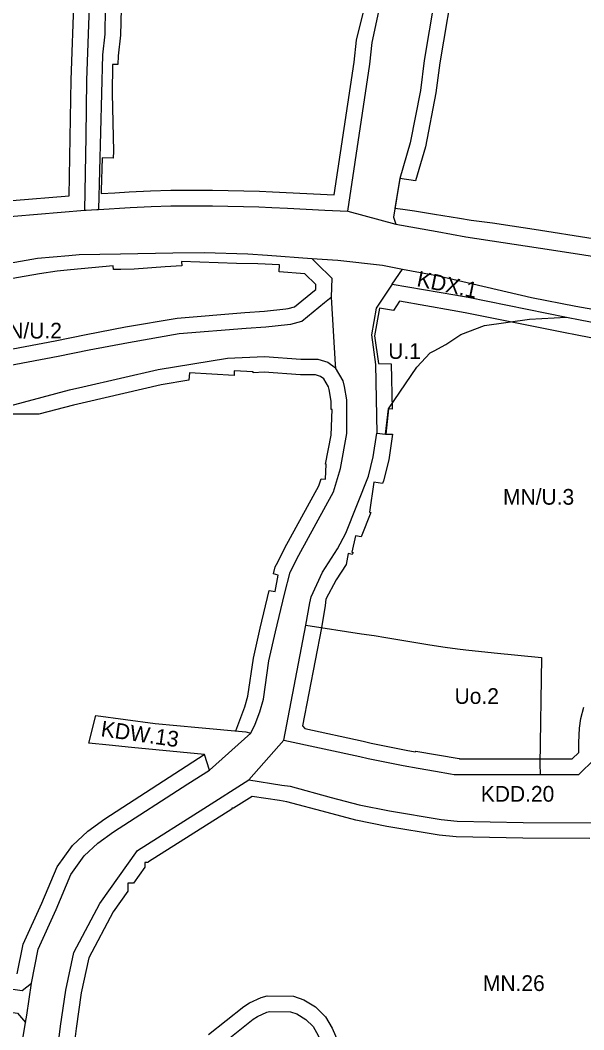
# Model space of a CAD drawing. Extents: x 7414808 to 7417449, y 5544732 to 5546764.
# Drawn here: x 7415895.6 to 7416075.2, y 5545739 to 5546060.4 of the extents above; entities that cross this region are included whole.
import ezdxf

# ---------------------------------------------------------------- set-up
doc = ezdxf.new("R2010")
doc.units = 0
for name, color, linetype in [('LIN_Linie Rozgraniczajace', 7, 'Continuous'), ('LIN_nieprzekraczale linie zabudowy', 7, 'Continuous'), ('TXT_Oznaczenia Przeznaczenia', 7, 'Continuous')]:
    doc.layers.add(name, color=color, linetype=linetype)

msp = doc.modelspace()

# ---------------------------------------------------------------- linework, layer by layer
at = {"layer": 'LIN_Linie Rozgraniczajace'}
msp.add_line((7415955.91, 5545821.67), (7415969.1, 5545833.41), dxfattribs=at)
for points in [[(7416000, 5545999.56), (7416007.01, 5546046.39), (7416007.77, 5546053.27), (7416011.53, 5546070.75), (7416012.03, 5546070.7), (7416016.43, 5546092.22), (7416015.51, 5546092.28), (7416019.25, 5546115.26), (7416019.68, 5546119.96), (7416020.64, 5546130.99), (7416021.01, 5546139.92), (7416020.58, 5546148.86), (7416019.36, 5546157.71), (7416017.52, 5546165.82), (7416014.43, 5546177.2), (7416012.98, 5546181.74)], [(7416031.71, 5546182.56), (7416032.23, 5546181.11), (7416034.82, 5546172.09), (7416036.63, 5546162.89), (7416037.66, 5546153.57), (7416037.89, 5546144.2), (7416037.31, 5546134.83), (7416036.47, 5546126.72), (7416035.62, 5546119.19), (7416034.78, 5546111.66), (7416032.88, 5546099.09), (7416032.19, 5546095.15), (7416030.26, 5546082.93), (7416029.17, 5546076.02), (7416024.41, 5546047.6), (7416023.18, 5546038.06), (7416019.9, 5546021.33), (7416016.59, 5546010.05), (7416014.56, 5545997.73), (7416015.33, 5545995.49)], [(7415918.71, 5546091.48), (7415918.95, 5546098.1), (7415919.91, 5546128.95), (7415920.03, 5546132.92), (7415929.03, 5546132.64), (7415928.75, 5546123.64), (7415924.7, 5546123.6), (7415924.31, 5546123.6), (7415924.15, 5546116.95), (7415924.02, 5546111.29), (7415923.61, 5546097.93), (7415923.01, 5546073.56), (7415922.63, 5546058.16), (7415922.58, 5546056.01), (7415921.81, 5546049.39), (7415920.6, 5546000.18)], [(7415916.2, 5545999.89), (7415916.6, 5546023.36), (7415916.91, 5546041.3), (7415918.4, 5546082.49)], [(7415886.52, 5545997.16), (7415893.57, 5545997.99), (7415916.2, 5545999.89)], [(7415916.2, 5545999.89), (7415916.7, 5545999.93), (7415920.1, 5546000.15), (7415920.6, 5546000.18)], [(7415920.6, 5546000.18), (7415930.62, 5546000.79), (7415937.38, 5546001.08), (7415943.66, 5546001.26), (7415956.86, 5546001.34), (7415971.69, 5546000.97), (7415975.83, 5546000.78), (7415980.77, 5546000.53), (7415992.69, 5545999.93), (7416000, 5545999.56)], [(7416000, 5545999.56), (7416015.33, 5545995.49)], [(7416015.33, 5545995.49), (7416028.49, 5545993.17), (7416037.64, 5545991.43), (7416064.98, 5545987.25), (7416085.59, 5545984.1), (7416096.65, 5545982.41), (7416109.87, 5545979.94), (7416111.59, 5545979.53)], [(7415844.76, 5545971.84), (7415852.47, 5545973.82), (7415865.1, 5545977.09), (7415866.9, 5545977.56), (7415880.97, 5545980.98), (7415882.96, 5545981.47), (7415901.09, 5545984.65), (7415911.16, 5545985.54), (7415914.44, 5545985.83), (7415927.64, 5545986.05), (7415944.27, 5545986.35), (7415954.23, 5545986.43), (7415968.21, 5545986.01), (7415974.4, 5545985.57), (7415988.52, 5545984.56)], [(7415988.52, 5545984.56), (7415990.15, 5545982.96), (7415994.96, 5545978.25), (7415994.76, 5545972.26)], [(7415988.52, 5545984.56), (7415996.88, 5545983.96), (7416011.04, 5545982.43), (7416017.42, 5545981.19)], [(7416014.2, 5545976.41), (7416017.42, 5545981.19)], [(7416017.42, 5545981.19), (7416028.93, 5545978.99), (7416058.62, 5545972.09), (7416072.75, 5545969.33), (7416083.51, 5545967.43), (7416094.03, 5545965.04), (7416101.56, 5545962.07), (7416102.47, 5545961.81)], [(7416014.2, 5545976.41), (7416009.05, 5545968.77), (7416007.57, 5545960.21), (7416008.83, 5545950.76), (7416009.25, 5545928.92)], [(7416014.2, 5545976.41), (7416034.13, 5545972.92), (7416038.34, 5545972.18), (7416069.77, 5545965.84)], [(7415844.58, 5545938.19), (7415852.82, 5545940.7), (7415871.18, 5545946.15), (7415888.53, 5545949.83), (7415907.71, 5545953.42), (7415917.62, 5545955.43), (7415930.1, 5545957.84), (7415946.29, 5545960.61), (7415967.66, 5545962.35), (7415973.92, 5545962.82), (7415980.78, 5545963.53), (7415981.89, 5545963.65), (7415985.36, 5545964.57), (7415992.58, 5545970.49), (7415994.76, 5545972.26)], [(7415994.76, 5545972.26), (7415996.05, 5545950.83), (7415996.13, 5545949.68)], [(7416009.25, 5545928.92), (7416012.07, 5545928.66), (7416012.96, 5545936.69), (7416022.02, 5545949.98), (7416026.33, 5545954.48), (7416027.55, 5545955.12), (7416031.3, 5545957.18), (7416036.08, 5545960.32), (7416043.63, 5545963.18), (7416057.92, 5545965.24), (7416069.77, 5545965.84)], [(7416069.77, 5545965.84), (7416074.06, 5545965.04), (7416086.23, 5545962.71), (7416095.68, 5545960.09), (7416099.01, 5545958.78), (7416101.22, 5545955.99), (7416101.99, 5545952.8)], [(7415887.87, 5545936.49), (7415911.39, 5545942.72), (7415915.59, 5545943.68), (7415939.59, 5545949.25), (7415961.67, 5545952.78), (7415973.46, 5545953.36), (7415985.11, 5545952.48), (7415986.01, 5545952.48), (7415990.47, 5545952.48), (7415993.62, 5545951.52), (7415996.13, 5545949.68)], [(7415969.1, 5545833.41), (7415970.5, 5545836.23), (7415971.99, 5545840.19), (7415973.12, 5545844.18), (7415974.88, 5545856.4), (7415977.01, 5545865.7), (7415979.86, 5545877.67), (7415981.63, 5545884.62), (7415984.42, 5545890.11), (7415995.48, 5545910.24), (7415997.72, 5545917.72), (7415999.71, 5545928.8), (7415999.76, 5545933.26), (7415999.67, 5545939.54), (7415998.98, 5545943.8), (7415998.56, 5545945.63), (7415996.13, 5545949.68)], [(7415986.69, 5545867.84), (7415987.97, 5545874.91), (7415988.31, 5545876.82), (7415991.93, 5545884.66), (7415996.76, 5545892.08), (7415999.35, 5545897.08), (7416006.63, 5545915.23), (7416008.16, 5545921.4), (7416009.25, 5545928.92)], [(7415979.67, 5545831.16), (7415986.69, 5545867.84)], [(7415986.69, 5545867.84), (7416004.35, 5545865.07), (7416008.39, 5545864.46), (7416012.15, 5545863.89), (7416026.14, 5545861.58), (7416031.07, 5545860.77), (7416035.04, 5545860.26), (7416037.64, 5545859.92), (7416046.72, 5545858.95), (7416061.74, 5545857.55), (7416061.28, 5545823.37), (7416061.31, 5545820.54), (7416061.31, 5545820.27)], [(7415955.91, 5545821.67), (7415954.34, 5545826.57), (7415931.12, 5545828.89), (7415923.99, 5545829.6), (7415917.5, 5545830.25), (7415919.7, 5545839.06), (7415938.62, 5545836.47), (7415952.46, 5545835.2), (7415967.56, 5545833.82), (7415969.1, 5545833.41)], [(7415968.5, 5545818.52), (7415979.67, 5545831.16)], [(7415979.67, 5545831.16), (7416003.85, 5545825.95), (7416006.48, 5545825.38), (7416017.69, 5545823.11), (7416022.48, 5545822.25), (7416027.93, 5545821.26), (7416032.74, 5545820.47), (7416033.95, 5545820.27), (7416061.31, 5545820.27)], [(7416061.31, 5545820.27), (7416073.62, 5545820.27), (7416078.62, 5545825.18)], [(7415899.18, 5545753.76), (7415901.32, 5545764.63), (7415907.1, 5545777.22), (7415911.78, 5545788.44), (7415916.04, 5545794.37), (7415920.33, 5545798.37), (7415925.36, 5545801.94), (7415949.1, 5545817.27), (7415955.91, 5545821.67)], [(7415907.51, 5545732.31), (7415908.48, 5545740.08), (7415910.18, 5545751.57), (7415912.74, 5545763.6), (7415920.96, 5545779.17), (7415933.01, 5545796.09), (7415954.12, 5545809.43), (7415968.5, 5545818.52)], [(7415968.5, 5545818.52), (7415979, 5545816.89), (7415981.64, 5545816.49), (7415994.71, 5545812.97), (7416003.69, 5545810.56), (7416013.36, 5545808.66), (7416029.77, 5545805.91), (7416034.85, 5545805.41), (7416055.87, 5545805.01), (7416080.18, 5545804.83), (7416081.41, 5545803.58)], [(7415668.24, 5545779.8), (7415672.05, 5545783.11), (7415685.34, 5545779.85), (7415697.83, 5545777.04), (7415710.13, 5545774.26), (7415722.57, 5545771.47), (7415731.5, 5545769.45), (7415736.13, 5545768.65), (7415748.95, 5545766.65), (7415761.72, 5545764.58), (7415774.82, 5545763.02), (7415795.49, 5545759.28), (7415821.27, 5545755.23), (7415823.26, 5545754.92), (7415847.35, 5545751.4), (7415871.95, 5545747.49), (7415894.72, 5545744.26), (7415897.34, 5545741.25)], [(7415785.08, 5545767.93), (7415793.95, 5545766.44), (7415805.7, 5545764.63), (7415823.54, 5545761.88), (7415841.33, 5545759.46), (7415848.19, 5545758.4), (7415896.23, 5545751.46), (7415899.18, 5545753.76)], [(7415897.34, 5545741.25), (7415897.69, 5545743.65), (7415899.18, 5545753.76)], [(7415907.51, 5545732.31), (7415910.16, 5545729.3), (7415930.83, 5545729.24), (7415946.27, 5545729.2), (7415950.24, 5545729.58), (7415954.06, 5545730.75), (7415957.57, 5545732.66), (7415958.68, 5545733.47), (7415969.92, 5545742.3), (7415971.21, 5545743.2), (7415974.2, 5545744.56), (7415975.03, 5545744.8), (7415981.8, 5545744.72), (7415983.83, 5545743.99), (7415986.63, 5545742.29), (7415988.94, 5545739.96), (7415990.61, 5545737.14), (7415992.94, 5545731.87)], [(7415894.25, 5545722.05), (7415894.28, 5545722.62), (7415897.34, 5545741.25)]]:
    msp.add_lwpolyline(points, dxfattribs=at)
at = {"layer": 'LIN_nieprzekraczale linie zabudowy'}
for points in [[(7415928.61, 5546097.79), (7415927.57, 5546055.67), (7415926.81, 5546049.04), (7415926.74, 5546046.3), (7415925.07, 5546046.28), (7415924.98, 5546037.1), (7415925.35, 5546018.76), (7415925.3, 5546016.5), (7415921.76, 5546016.64), (7415921.42, 5546006.21), (7415921.4, 5546005.24), (7415925.74, 5546005.5), (7415930.36, 5546005.79), (7415937.2, 5546006.08), (7415943.58, 5546006.26), (7415956.91, 5546006.34), (7415971.87, 5546005.97), (7415976.07, 5546005.78), (7415995.73, 5546004.78), (7416002.05, 5546047.02), (7416002.83, 5546054.07), (7416002.83, 5546054.07), (7416007.15, 5546071.79)], [(7415889.54, 5546041.99), (7415889.13, 5546024), (7415888.94, 5546015.32), (7415885.81, 5546015.38), (7415885.66, 5546009.07), (7415888.79, 5546008.99), (7415888.64, 5546002.44), (7415893.07, 5546002.97), (7415911.27, 5546004.49), (7415911.91, 5546041.44), (7415913.83, 5546094.61)], [(7416034.1, 5546075.19), (7416029.36, 5546046.87), (7416028.12, 5546037.26), (7416024.76, 5546020.14), (7416021.59, 5546009.32), (7416016.59, 5546010.05), (7416015.02, 5546000.53), (7416017.53, 5546000.26), (7416021.28, 5545999.67), (7416027.68, 5545998.65), (7416035.58, 5545997.38), (7416039.37, 5545996.77), (7416046.12, 5545995.94), (7416052.36, 5545994.91), (7416059.46, 5545993.83), (7416078.18, 5545990.91)], [(7415887.55, 5545954.73), (7415906.75, 5545958.33), (7415916.65, 5545960.33), (7415929.2, 5545962.76), (7415945.67, 5545965.58), (7415967.26, 5545967.34), (7415973.48, 5545967.8), (7415980.25, 5545968.5), (7415980.98, 5545968.58), (7415983.03, 5545969.12), (7415989.42, 5545974.36), (7415989.84, 5545974.7), (7415989.89, 5545976.22), (7415986.33, 5545979.7), (7415978.21, 5545980.28), (7415978.3, 5545982.57), (7415971.39, 5545982.85), (7415964.55, 5545982.93), (7415947.05, 5545983.56), (7415947.09, 5545982.19), (7415941.82, 5545981.89), (7415931.94, 5545981.12), (7415927.73, 5545981.05), (7415925.4, 5545981.01), (7415925.4, 5545981.01), (7415925.27, 5545982.24), (7415911.7, 5545980.9), (7415907.36, 5545980.46), (7415901.74, 5545979.69), (7415883.99, 5545976.57)], [(7416016.53, 5545970.93), (7416014.57, 5545968.02), (7416010.14, 5545968.71), (7416008.56, 5545959.95), (7416009.86, 5545951.16), (7416013.83, 5545950.98), (7416014.13, 5545936.58), (7416012.96, 5545936.69), (7416012.12, 5545928.66), (7416014.25, 5545928.59), (7416013.07, 5545920.44), (7416011.4, 5545913.7), (7416011.08, 5545912.9), (7416008.35, 5545913.28), (7416006.98, 5545903.72), (7416007.38, 5545903.67), (7416004.27, 5545895.92), (7416002.49, 5545896.26), (7416001.32, 5545891), (7416001.78, 5545890.9), (7416001.47, 5545890.31), (7416000.1, 5545890.56), (7415999.47, 5545887.08), (7415996.32, 5545882.23), (7415993.05, 5545876.02), (7415992.77, 5545874.1), (7415991.61, 5545866.95), (7415991.6, 5545866.9), (7415985.63, 5545835.73), (7415986.3, 5545834.85), (7416004.91, 5545830.84), (7416007.51, 5545830.27), (7416018.63, 5545828.02), (7416021.5, 5545827.51), (7416021.73, 5545827.65), (7416035.55, 5545825.32), (7416035.58, 5545825.27), (7416071.58, 5545825.27), (7416073.63, 5545827.28), (7416073.63, 5545830.46), (7416073.84, 5545835.01), (7416074.32, 5545838.05), (7416075.26, 5545841.64)], [(7416101.12, 5545947.88), (7416096.01, 5545949.52), (7416096.84, 5545952.82), (7416096.62, 5545953.75), (7416095.93, 5545954.62), (7416094.09, 5545955.34), (7416085.09, 5545957.84), (7416073.13, 5545960.12), (7416068.82, 5545960.93), (7416037.41, 5545967.27), (7416033.27, 5545968), (7416016.53, 5545970.93)], [(7415964.36, 5545834.11), (7415967.24, 5545841.75), (7415968.22, 5545845.22), (7415969.96, 5545857.32), (7415972.14, 5545866.84), (7415975.01, 5545878.87), (7415976.83, 5545878.53), (7415977.8, 5545883.75), (7415976.34, 5545884.09), (7415976.34, 5545884.09), (7415976.92, 5545886.39), (7415977.27, 5545887.07), (7415979.18, 5545890.83), (7415980, 5545892.45), (7415990.84, 5545912.19), (7415991.49, 5545914.36), (7415992.92, 5545914.33), (7415993.16, 5545919.05), (7415992.89, 5545919.09), (7415994.72, 5545928.33), (7415995.03, 5545936.46), (7415994.71, 5545936.47), (7415994.68, 5545939.1), (7415994.07, 5545942.84), (7415993.86, 5545943.73), (7415992.36, 5545946.24), (7415991.35, 5545946.99), (7415989.73, 5545947.48), (7415984.92, 5545947.48), (7415973.4, 5545948.35), (7415969.87, 5545948.18), (7415969.88, 5545948.49), (7415963.85, 5545948.8), (7415963.79, 5545947.31), (7415949.54, 5545948.12), (7415949.37, 5545945.75), (7415940.55, 5545944.34), (7415916.71, 5545938.81), (7415912.59, 5545937.86), (7415901.54, 5545934.94), (7415887.66, 5545934.96)], [(7415894.67, 5545756.74), (7415896.53, 5545766.18), (7415902.52, 5545779.23), (7415907.39, 5545790.89), (7415912.27, 5545797.69), (7415917.16, 5545802.25), (7415922.56, 5545806.08), (7415954.25, 5545826.58)], [(7416077.12, 5545799.85), (7416055.8, 5545800.01), (7416034.56, 5545800.41), (7416029.11, 5545800.95), (7416012.46, 5545803.74), (7416002.56, 5545805.69), (7415993.41, 5545808.14), (7415980.61, 5545811.59), (7415978.24, 5545811.95), (7415969.59, 5545813.29), (7415963.62, 5545809.52), (7415963.08, 5545809.53), (7415963.07, 5545809.17), (7415936.51, 5545792.39), (7415936.4, 5545792.23), (7415935.34, 5545792.24), (7415935.35, 5545790.76), (7415931.7, 5545785.64), (7415929.89, 5545785.65), (7415929.88, 5545783.08), (7415925.23, 5545776.54), (7415917.49, 5545761.88), (7415915.1, 5545750.68), (7415913.43, 5545739.4), (7415912.8, 5545734.29)], [(7415955.66, 5545737.46), (7415966.94, 5545746.33), (7415968.73, 5545747.56), (7415972.47, 5545749.27), (7415974.37, 5545749.81), (7415982.69, 5545749.71), (7415985.99, 5545748.53), (7415989.75, 5545746.24), (7415992.92, 5545743.04), (7415995.07, 5545739.43), (7415997.51, 5545733.89)]]:
    msp.add_lwpolyline(points, dxfattribs=at)

# ---------------------------------------------------------------- texts
at = {"layer": 'TXT_Oznaczenia Przeznaczenia'}
for s, rotation, p in [('KDX.1', 348.3326, (7416021.77, 5545975.78)), ('KDW.13', 351.8055, (7415921.12, 5545832.46))]:
    msp.add_text(s, height=5, rotation=rotation, dxfattribs=at).set_placement(p)
for s, p in [('MN/U.2', (7415886.25, 5545959.07)), ('U.1', (7416012.91, 5545952.57)), ('MN/U.3', (7416049.51, 5545906.15)), ('Uo.2', (7416034.06, 5545842.73)), ('KDD.20', (7416042.42, 5545811.59)), ('MN.26', (7416043.1, 5545751.31))]:
    msp.add_text(s, height=5, dxfattribs=at).set_placement(p)

doc.saveas('drawing.dxf')
